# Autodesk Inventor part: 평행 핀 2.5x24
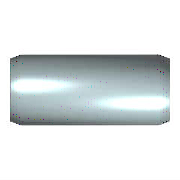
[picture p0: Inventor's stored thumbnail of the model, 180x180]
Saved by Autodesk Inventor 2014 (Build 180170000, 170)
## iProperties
Created: 2012-02
Part Number: 평행 핀 2.5x24
Material: 강철, 연강
Description: 평행 핀
Document SubType Name: Modeling
Standard: KS B 1320
Designer: mduedu
Standards Organization: KS
Language: ko-KR
Size Designation: B 2.5 x  24
Categories: <MemberInstance><Categories><Category DisplayName="조임쇠" InternalName="e4da775c-781d-43d5-af7c-5136215cf5a6" Mnemonic="FSTN"><Category DisplayName="핀" InternalNa
Density: 1 g/cm^3
Appearance: 노란색
IsCustomPart: 1
Author: mduedu
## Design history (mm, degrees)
sketch "스케치"
  geometry: C1 r 1.25 at (0, 0); 1 further point
  constraints: 1 centre point, 1 coincident
  dimensions: "d1" = 2.5 diameter of C1 (= NND)
extrude "본체" new body sketch "스케치" distance "d2" = 24 (= NLG); taper "d3" = 0 deg
chamfer "스케치2" distance "d8" = 0.4 (= PHH); stored, may be unused: angle "d9" = 15 deg (= FAWI), second distance "d12" = 0.4 (= PHH)
node "작업 평면1"
body "Solid1"
chamfer "모따기1" distance "d4" = 0.4 (= PHH); stored, may be unused: angle "d5" = 15 deg (= FAWI), second distance "d11" = 0.4 (= PHH)
other parameters: "NND" = 2.5 [user parameter; used in 1 equation term], "NLG" = 24 [user parameter; used in 1 equation term], "PHH" = 0.4 [user parameter; used in 4 equation terms], "FAWI" = 15 deg [user parameter; used in 2 equation terms], "d13" = 0, "d15" = 0, "d16" = 0, "KAH" = 0.3 [user parameter]
